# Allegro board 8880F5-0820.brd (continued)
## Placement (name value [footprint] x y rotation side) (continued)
NOREF#876  -  []  327.57 204.65 90 top
NOREF#877  -  []  96.33 238.84 0 top
NOREF#878  -  []  351.58 288.86 0 top
NOREF#879  -  []  168.13 132.17 90 top
NOREF#880  -  []  339.33 204.35 90 top
NOREF#881  -  []  310.43 243.09 90 top
NOREF#882  -  []  182.82 216.47 90 top
NOREF#883  -  []  122.15 187.53 0 top
NOREF#884  -  []  414.25 154.88 0 top
NOREF#885  -  []  465.31 186.77 0 top
NOREF#886  -  []  118.33 273.87 90 top
NOREF#887  -  []  273.5 148.65 90 top
NOREF#888  -  []  263.95 224.74 90 top
NOREF#889  -  []  313.56 144.34 90 top
NOREF#890  -  []  309.05 211.67 0 top
NOREF#891  -  []  124.1 238.84 0 top
NOREF#892  -  []  333.4 205.55 0 top
NOREF#893  -  []  272.24 243.59 90 top
NOREF#894  -  []  327.25 265.55 0 top
NOREF#895  -  []  410.52 241.11 0 top
NOREF#896  -  []  405.42 131.94 90 top
NOREF#897  -  []  317.83 257.63 0 top
NOREF#898  -  []  353.35 288.31 90 top
NOREF#899  -  []  167.7 200.54 0 top
NOREF#900  -  []  230.41 188.88 90 top
NOREF#901  -  []  167.7 233.47 90 top
NOREF#902  -  []  261.21 286.96 0 top
NOREF#903  -  []  184.47 173.11 0 top
NOREF#904  -  []  396.22 139.89 0 top
NOREF#905  -  []  392.47 272.56 90 top
NOREF#906  -  []  309.21 253.37 0 top
NOREF#907  -  []  390.53 146.88 0 top
NOREF#908  -  []  118.33 289.48 90 top
NOREF#909  -  []  379.48 222.7 90 top
NOREF#910  -  []  262.36 225.04 90 top
NOREF#911  -  []  275.3 155.38 0 top
NOREF#912  -  []  392.73 188.15 0 top
NOREF#913  -  []  166.06 203.01 90 top
NOREF#914  -  []  324.65 288.86 0 top
NOREF#915  -  []  118.99 171.65 0 top
NOREF#916  -  []  220.36 188.49 0 top
NOREF#917  -  []  351.34 245.18 0 top
NOREF#918  -  []  175.7 164.3 90 top
NOREF#919  -  []  405.93 224.66 90 top
NOREF#920  -  []  367.13 287.22 0 top
NOREF#921  -  []  256.77 225.04 90 top
NOREF#922  -  []  410.52 273.37 0 top
NOREF#923  -  []  390.53 188.15 0 top
NOREF#924  -  []  408.02 271.47 0 top
NOREF#925  -  []  343.2 172.26 90 top
NOREF#926  -  []  230.73 189.2 0 top
NOREF#927  -  []  376.98 257.11 0 top
NOREF#928  -  []  332.51 265.55 0 top
NOREF#929  -  []  339.65 205.86 90 top
NOREF#930  -  []  419.65 256.92 90 top
NOREF#931  -  []  168.69 290.01 90 top
NOREF#932  -  []  185.2 276.04 90 top
NOREF#933  -  []  201.23 219.75 90 top
NOREF#934  -  []  265.81 288.86 0 top
NOREF#935  -  []  167.7 178.86 90 top
NOREF#936  -  []  309.51 187.93 0 top
NOREF#937  -  []  223.56 245.29 90 top
NOREF#938  -  []  177.33 146.68 90 top
NOREF#939  -  []  238.45 257.01 0 top
NOREF#940  -  []  230.73 246.66 0 top
NOREF#941  -  []  118.45 239.39 0 top
NOREF#942  -  []  448.94 276.41 90 top
NOREF#943  -  []  334.29 205.56 0 top
NOREF#944  -  []  184.47 241.43 90 top
NOREF#945  -  []  419.9 154.88 0 top
NOREF#946  -  []  388.35 217.36 0 top
NOREF#947  -  []  250.49 163.52 90 top
NOREF#948  -  []  395.2 233.11 0 top
NOREF#949  -  []  272.25 241.69 0 top
NOREF#950  -  []  339.33 205.55 0 top
NOREF#951  -  []  229.05 211.67 0 top
NOREF#952  -  []  352.25 244.23 0 top
NOREF#953  -  []  373.87 171.39 0 top
NOREF#954  -  []  201.49 159.65 90 top
NOREF#955  -  []  379.52 171.39 0 top
NOREF#956  -  []  259.88 288.41 90 top
NOREF#957  -  []  100.73 238.84 0 top
NOREF#958  -  []  184.47 145.93 0 top
NOREF#959  -  []  373.83 192.28 90 top
NOREF#960  -  []  310.43 189.52 0 top
NOREF#961  -  []  337.9 246.99 0 top
NOREF#962  -  []  277.17 288.86 0 top
NOREF#963  -  []  399.99 181.42 90 top
NOREF#964  -  []  352.25 242.32 90 top
NOREF#965  -  []  117.33 247.35 90 top
NOREF#966  -  []  209.23 189.02 90 top
NOREF#967  -  []  257.09 164.74 90 top
NOREF#968  -  []  408.88 133.16 90 top
NOREF#969  -  []  254.61 264.65 90 top
NOREF#970  -  []  201.23 217.55 90 top
NOREF#971  -  []  419.47 289.12 90 top
NOREF#972  -  []  252.51 205.56 0 top
NOREF#973  -  []  192.47 205.19 90 top
NOREF#974  -  []  310.43 246.34 90 top
NOREF#975  -  []  250.73 265.56 0 top
NOREF#976  -  []  200.98 255.15 90 top
NOREF#977  -  []  403.41 209.61 0 top
NOREF#978  -  []  462.06 293.82 90 top
NOREF#979  -  []  317.83 197.63 0 top
NOREF#980  -  []  343.31 164.74 0 top
NOREF#981  -  []  333.4 265.56 90 top
NOREF#982  -  []  419.4 171.64 0 top
NOREF#983  -  []  201.23 244.98 90 top
NOREF#984  -  []  339.46 288.86 90 top
NOREF#985  -  []  310.43 194.01 0 top
NOREF#986  -  []  383.09 289.12 0 top
NOREF#987  -  []  106.11 234.24 0 top
NOREF#988  -  []  184.47 161 90 top
NOREF#989  -  []  250.73 265.56 90 top
NOREF#990  -  []  257.08 132.19 90 top
NOREF#991  -  []  410.52 289.12 0 top
NOREF#992  -  []  302.11 240.71 0 top
NOREF#993  -  []  473.7 219.66 90 top
NOREF#994  -  []  461.86 187.32 0 top
NOREF#995  -  []  184.47 200.54 90 top
NOREF#996  -  []  192.47 216.45 90 top
NOREF#997  -  []  346.69 128.87 90 top
NOREF#998  -  []  377.23 224.65 90 top
NOREF#999  -  []  251.94 204.65 90 top
NOREF#1000  -  []  352.55 185.18 0 top
NOREF#1001  -  []  334.61 264.65 90 top
NOREF#1002  -  []  371.48 249.11 0 top
NOREF#1003  -  []  463.11 230.2 0 top
NOREF#1004  -  []  405.51 209.61 0 top
NOREF#1005  -  []  417.87 257.37 0 top
NOREF#1006  -  []  265.81 296.86 0 top
NOREF#1007  -  []  124.1 231.22 0 top
NOREF#1008  -  []  199.59 230.19 90 top
NOREF#1009  -  []  320.94 211.63 90 top
NOREF#1010  -  []  275.82 296.86 0 top
NOREF#1011  -  []  332.51 204.35 90 top
NOREF#1012  -  []  312.21 144.34 0 top
NOREF#1013  -  []  396.03 180.15 0 top
NOREF#1014  -  []  192.47 209.49 90 top
NOREF#1015  -  []  327.25 205.55 0 top
NOREF#1016  -  []  341.63 255.43 90 top
NOREF#1017  -  []  401.89 163.64 0 top
NOREF#1018  -  []  246.23 173.13 0 top
NOREF#1019  -  []  239.33 243.63 90 top
NOREF#1020  -  []  410.27 257.37 0 top
NOREF#1021  -  []  383.09 241.11 0 top
NOREF#1022  -  []  352.25 182.96 0 top
NOREF#1023  -  []  266.74 143.19 0 top
NOREF#1024  -  []  405.5 289.12 90 top
NOREF#1025  -  []  310.43 247.61 90 top
NOREF#1026  -  []  478.57 277.31 90 top
NOREF#1027  -  []  115.99 130.36 90 top
NOREF#1028  -  []  414.82 281.37 0 top
NOREF#1029  -  []  378.58 289.12 90 top
NOREF#1030  -  []  408.02 239.21 0 top
NOREF#1031  -  []  419.9 288.57 90 top
NOREF#1032  -  []  330.74 164.74 0 top
NOREF#1033  -  []  194.09 214.75 90 top
NOREF#1034  -  []  331.62 205.55 0 top
NOREF#1035  -  []  330.51 288.86 0 top
NOREF#1036  -  []  172.08 275.14 90 top
NOREF#1037  -  []  175.7 150.58 90 top
NOREF#1038  -  []  155.57 289.11 90 top
NOREF#1039  -  []  453.88 195.91 0 top
NOREF#1040  -  []  395.2 297.12 0 top
NOREF#1041  -  []  309.21 247.61 0 top
NOREF#1042  -  []  385.32 178.25 90 top
NOREF#1043  -  []  297.83 174.63 90 top
NOREF#1044  -  []  237.66 224.74 0 top
NOREF#1045  -  []  221.56 231.46 0 top
NOREF#1046  -  []  352.25 182.32 90 top
NOREF#1047  -  []  300.74 286.96 90 top
NOREF#1048  -  []  275.28 290.13 90 top
NOREF#1049  -  []  201.23 229.07 90 top
NOREF#1050  -  []  400.85 249.11 0 top
NOREF#1051  -  []  209.49 175.56 90 top
NOREF#1052  -  []  387.39 297.12 0 top
NOREF#1053  -  []  249.28 165.04 90 top
NOREF#1054  -  []  396.55 273.11 0 top
NOREF#1055  -  []  386.53 148.15 90 top
NOREF#1056  -  []  383.09 257.11 0 top
NOREF#1057  -  []  272.24 182.32 90 top
NOREF#1058  -  []  217.41 273.24 90 top
NOREF#1059  -  []  270.04 280.1 0 top
NOREF#1060  -  []  106.36 190.55 0 top
NOREF#1061  -  []  395.2 265.37 0 top
NOREF#1062  -  []  272.25 242.32 90 top
NOREF#1063  -  []  343.31 224.72 0 top
NOREF#1064  -  []  473.79 234.49 90 top
NOREF#1065  -  []  118.96 179.19 0 top
NOREF#1066  -  []  418.37 289.17 90 top
NOREF#1067  -  []  230.41 193.37 90 top
NOREF#1068  -  []  394.05 255.47 0 top
NOREF#1069  -  []  127.81 175.44 90 top
NOREF#1070  -  []  450.03 225.6 0 top
NOREF#1071  -  []  352.25 243.59 90 top
NOREF#1072  -  []  167.7 260.9 90 top
NOREF#1073  -  []  167.7 187.92 90 top
NOREF#1074  -  []  167.7 227.72 90 top
NOREF#1075  -  []  310.43 187.61 90 top
NOREF#1076  -  []  175.7 205.19 90 top
NOREF#1077  -  []  390.69 241.11 0 top
NOREF#1078  -  []  247.25 265.56 0 top
NOREF#1079  -  []  415.08 139.89 0 top
NOREF#1080  -  []  330.17 165.04 90 top
NOREF#1081  -  []  251.38 163.52 90 top
NOREF#1082  -  []  318.3 163.52 90 top
NOREF#1083  -  []  94.93 190.55 0 top
NOREF#1084  -  []  333.4 265.56 0 top
NOREF#1085  -  []  168.13 159.1 90 top
NOREF#1086  -  []  166.06 148.4 90 top
NOREF#1087  -  []  108.01 222.33 0 top
NOREF#1088  -  []  367.13 271.21 0 top
NOREF#1089  -  []  396.55 225.11 0 top
NOREF#1090  -  []  311.44 288.86 0 top
NOREF#1091  -  []  368.28 297.12 0 top
NOREF#1092  -  []  237.98 225.04 90 top
NOREF#1093  -  []  248.96 164.74 0 top
NOREF#1094  -  []  318.32 131.64 0 top
NOREF#1095  -  []  230.83 224.63 0 top
NOREF#1096  -  []  303.56 173.86 90 top
NOREF#1097  -  []  401.87 139.89 0 top
NOREF#1098  -  []  192.47 222.95 90 top
NOREF#1099  -  []  352.55 189.5 0 top
NOREF#1100  -  []  475.04 195.66 0 top
NOREF#1101  -  []  238.45 197.01 0 top
NOREF#1102  -  []  327.57 264.65 90 top
NOREF#1103  -  []  282.9 147.38 0 top
NOREF#1104  -  []  247.57 204.65 90 top
NOREF#1105  -  []  271.34 189.5 0 top
NOREF#1106  -  []  209.23 236.67 90 top
NOREF#1107  -  []  247.25 265.55 0 top
NOREF#1108  -  []  107.02 174.04 90 top
NOREF#1109  -  []  377.32 188.15 0 top
NOREF#1110  -  []  404.15 257.37 0 top
NOREF#1111  -  []  377.23 289.12 0 top
NOREF#1112  -  []  404.4 225.16 90 top
NOREF#1113  -  []  93.76 271.33 90 top
NOREF#1114  -  []  119.99 214.79 0 top
NOREF#1115  -  []  309.51 186.66 0 top
NOREF#1116  -  []  223.15 211.32 90 top
NOREF#1117  -  []  334.29 265.56 90 top
NOREF#1118  -  []  309.51 249.2 0 top
NOREF#1119  -  []  310.41 247.61 90 top
NOREF#1120  -  []  343.98 288.86 0 top
NOREF#1121  -  []  75.98 290.38 90 top
NOREF#1122  -  []  209.59 147.43 90 top
NOREF#1123  -  []  423.71 181.22 90 top
NOREF#1124  -  []  182.57 185.42 90 top
NOREF#1125  -  []  209.33 215.25 90 top
NOREF#1126  -  []  182.57 226.57 0 top
NOREF#1127  -  []  215.96 248.49 0 top
NOREF#1128  -  []  167.7 219.75 90 top
NOREF#1129  -  []  252.51 204.35 90 top
NOREF#1130  -  []  305.94 296.86 0 top
NOREF#1131  -  []  184.47 229.07 90 top
NOREF#1132  -  []  342.36 223.82 90 top
NOREF#1133  -  []  192.47 168.6 90 top
NOREF#1134  -  []  75.98 271.33 90 top
NOREF#1135  -  []  419.22 257.37 90 top
NOREF#1136  -  []  184.47 217.55 90 top
NOREF#1137  -  []  481.96 276.41 90 top
NOREF#1138  -  []  300.01 288.41 90 top
NOREF#1139  -  []  418.12 257.42 90 top
NOREF#1140  -  []  415.1 163.64 0 top
NOREF#1141  -  []  327.27 131.64 90 top
NOREF#1142  -  []  230.43 253.37 90 top
NOREF#1143  -  []  468.85 259.9 90 top
NOREF#1144  -  []  248.96 224.72 0 top
NOREF#1145  -  []  396.55 257.37 0 top
NOREF#1146  -  []  388.43 163.64 0 top
NOREF#1147  -  []  118.33 271.33 90 top
NOREF#1148  -  []  475.04 239.09 0 top
NOREF#1149  -  []  200.98 258.7 90 top
NOREF#1150  -  []  411.26 209.66 90 top
NOREF#1151  -  []  329.85 224.72 0 top
NOREF#1152  -  []  326.23 173.13 0 top
NOREF#1153  -  []  298.16 248.49 0 top
NOREF#1154  -  []  387.08 188.15 0 top
NOREF#1155  -  []  107.76 238.84 0 top
NOREF#1156  -  []  199.33 185.42 0 top
NOREF#1157  -  []  167.7 190.12 90 top
NOREF#1158  -  []  110.47 178.64 0 top
NOREF#1159  -  []  184.47 149.48 90 top
NOREF#1160  -  []  273.95 147.38 90 top
NOREF#1161  -  []  201.49 161 90 top
NOREF#1162  -  []  101.82 290.38 90 top
NOREF#1163  -  []  215.96 177.06 0 top
NOREF#1164  -  []  397.8 146.33 90 top
NOREF#1165  -  []  330.73 265.56 90 top
NOREF#1166  -  []  326.43 288.31 90 top
NOREF#1167  -  []  263.31 224.72 0 top
NOREF#1168  -  []  392.21 131.94 90 top
NOREF#1169  -  []  253.4 205.55 0 top
NOREF#1170  -  []  273.09 288.31 90 top
NOREF#1171  -  []  310.41 246.34 90 top
NOREF#1172  -  []  303.15 271.32 90 top
NOREF#1173  -  []  175.7 246.08 90 top
NOREF#1174  -  []  271.04 241.69 0 top
NOREF#1175  -  []  172.08 289.11 90 top
NOREF#1176  -  []  232.25 271.67 90 top
NOREF#1177  -  []  167.7 219.75 90 top
NOREF#1178  -  []  230.41 243.09 90 top
NOREF#1179  -  []  250.74 224.74 0 top
NOREF#1180  -  []  252.83 205.86 90 top
NOREF#1181  -  []  327.25 205.56 90 top
NOREF#1182  -  []  237.66 224.72 0 top
NOREF#1183  -  []  319.33 176.03 0 top
NOREF#1184  -  []  167.7 174.46 90 top
NOREF#1185  -  []  412.36 209.61 90 top
NOREF#1186  -  []  284.79 272.65 90 top
NOREF#1187  -  []  398.65 265.37 0 top
NOREF#1188  -  []  116.01 222.33 0 top
NOREF#1189  -  []  341.63 173.83 90 top
NOREF#1190  -  []  259.33 204.35 90 top
NOREF#1191  -  []  406.65 287.22 90 top
NOREF#1192  -  []  298.24 288.86 0 top
NOREF#1193  -  []  201.23 214 0 top
NOREF#1194  -  []  192.47 177.76 90 top
NOREF#1195  -  []  272.25 189.82 0 top
NOREF#1196  -  []  248.33 187.93 0 top
NOREF#1197  -  []  346.27 129.42 0 top
NOREF#1198  -  []  249.85 164.72 0 top
NOREF#1199  -  []  332.83 265.86 90 top
NOREF#1200  -  []  385.19 257.11 0 top
NOREF#1201  -  []  242.23 173.13 90 top
NOREF#1202  -  []  394.05 287.22 0 top
NOREF#1203  -  []  310.43 253.37 0 top
NOREF#1204  -  []  393.74 131.34 90 top
NOREF#1205  -  []  463.61 214.96 0 top
NOREF#1206  -  []  263.31 164.74 0 top
NOREF#1207  -  []  383.83 194.68 90 top
NOREF#1208  -  []  215.96 248.49 0 top
NOREF#1209  -  []  385.19 289.12 0 top
NOREF#1210  -  []  167.7 244.98 90 top
NOREF#1211  -  []  259.65 264.65 90 top
NOREF#1212  -  []  372.72 161.49 0 top
NOREF#1213  -  []  259.33 205.55 0 top
NOREF#1214  -  []  304.61 144.34 0 top
NOREF#1215  -  []  465.45 273.87 90 top
NOREF#1216  -  []  308.91 139.64 0 top
NOREF#1217  -  []  301.34 286.96 0 top
NOREF#1218  -  []  239.4 296.61 0 top
NOREF#1219  -  []  182.82 148.4 90 top
NOREF#1220  -  []  127.95 195.15 0 top
NOREF#1221  -  []  352.55 245.18 0 top
NOREF#1222  -  []  352.24 182.32 90 top
NOREF#1223  -  []  229.51 249.2 0 top
NOREF#1224  -  []  249.6 224.74 90 top
NOREF#1225  -  []  371.73 289.12 0 top
NOREF#1226  -  []  369.63 273.11 0 top
NOREF#1227  -  []  177.33 187.32 90 top
NOREF#1228  -  []  552.76 299.72 0 top
NOREF#1229  -  []  127.7 231.22 0 top
NOREF#1230  -  []  106.18 160.58 90 top
NOREF#1231  -  []  182.82 189.04 90 top
NOREF#1232  -  []  304.65 211.67 0 top
NOREF#1233  -  []  398.65 249.11 0 top
NOREF#1234  -  []  312.25 271.67 90 top
NOREF#1235  -  []  310.73 193.69 0 top
NOREF#1236  -  []  397.57 131.89 0 top
NOREF#1237  -  []  167.7 241.43 90 top
NOREF#1238  -  []  278.6 147.38 0 top
NOREF#1239  -  []  166.06 162.12 90 top
NOREF#1240  -  []  330.73 205.56 0 top
NOREF#1241  -  []  251.62 265.56 90 top
NOREF#1242  -  []  167.7 178.86 90 top
NOREF#1243  -  []  393.19 271.21 90 top
NOREF#1244  -  []  230.43 187.61 0 top
NOREF#1245  -  []  182.82 162.12 90 top
NOREF#1246  -  []  221.56 239.06 0 top
NOREF#1247  -  []  168.69 276.04 90 top
NOREF#1248  -  []  485.36 259.9 90 top
NOREF#1249  -  []  413.96 182.44 90 top
NOREF#1250  -  []  167.7 256.5 90 top
NOREF#1251  -  []  172.08 272.6 90 top
NOREF#1252  -  []  386.46 139.89 0 top
NOREF#1253  -  []  256.77 163.82 90 top
NOREF#1254  -  []  329.6 164.74 90 top
NOREF#1255  -  []  192.57 256.4 90 top
NOREF#1256  -  []  263.71 288.86 0 top
NOREF#1257  -  []  410.78 131.89 0 top
NOREF#1258  -  []  351.04 245.5 0 top
NOREF#1259  -  []  332.83 264.65 90 top
NOREF#1260  -  []  379 272.56 90 top
NOREF#1261  -  []  124.39 214.79 0 top
NOREF#1262  -  []  404.24 154.88 0 top
NOREF#1263  -  []  36.1 129.71 90 top
NOREF#1264  -  []  304.65 271.67 0 top
NOREF#1265  -  []  351.04 185.5 0 top
NOREF#1266  -  []  331.06 163.82 90 top
NOREF#1267  -  []  406.94 131.34 90 top
NOREF#1268  -  []  271.34 249.5 0 top
NOREF#1269  -  []  306.71 152.34 0 top
NOREF#1270  -  []  184.89 145.38 90 top
NOREF#1271  -  []  199.84 175.58 90 top
NOREF#1272  -  []  398.53 161.74 90 top
NOREF#1273  -  []  271.82 134.74 90 top
NOREF#1274  -  []  192.57 147.18 90 top
NOREF#1275  -  []  201.23 186.57 90 top
NOREF#1276  -  []  199.33 226.57 90 top
NOREF#1277  -  []  184.47 206.29 90 top
NOREF#1278  -  []  317.66 224.74 0 top
NOREF#1279  -  []  341.63 233.83 90 top
NOREF#1280  -  []  210.86 187.32 90 top
NOREF#1281  -  []  450.03 191.31 0 top
NOREF#1282  -  []  387.39 249.11 0 top
NOREF#1283  -  []  453.88 239.34 0 top
NOREF#1284  -  []  209.49 148.63 90 top
NOREF#1285  -  []  450.03 225.6 0 top
NOREF#1286  -  []  414.82 297.12 0 top
NOREF#1287  -  []  399.8 207.46 90 top
NOREF#1288  -  []  175.7 232.37 90 top
NOREF#1289  -  []  383.09 273.11 0 top
NOREF#1290  -  []  36.1 131.91 0 top
NOREF#1291  -  []  230.73 193.69 0 top
NOREF#1292  -  []  398.65 209.36 90 top
NOREF#1293  -  []  308.36 202.16 45 top
NOREF#1294  -  []  385.19 232.85 0 top
NOREF#1295  -  []  351.34 183.91 0 top
NOREF#1296  -  []  118.7 182.93 90 top
NOREF#1297  -  []  201.23 242.78 90 top
NOREF#1298  -  []  333.4 204.35 90 top
NOREF#1299  -  []  406.65 271.21 90 top
NOREF#1300  -  []  167.7 192.32 90 top
NOREF#1301  -  []  418.37 273.42 90 top
NOREF#1302  -  []  270.04 280.1 0 top
NOREF#1303  -  []  167.7 201.89 90 top
NOREF#1304  -  []  310.41 188.88 90 top
NOREF#1305  -  []  425.23 180.72 90 top
NOREF#1306  -  []  284.36 272.1 90 top
NOREF#1307  -  []  226.44 294.64 90 top
NOREF#1308  -  []  116.27 178.64 0 top
NOREF#1309  -  []  329.85 164.74 0 top
NOREF#1310  -  []  182.82 243.9 90 top
NOREF#1311  -  []  304.61 144.34 0 top
NOREF#1312  -  []  390.94 224.9 90 top
NOREF#1313  -  []  209.23 209.49 90 top
NOREF#1314  -  []  380.59 287.22 0 top
NOREF#1315  -  []  251.33 140.14 0 top
NOREF#1316  -  []  167.7 217.55 90 top
NOREF#1317  -  []  272.25 182.32 90 top
NOREF#1318  -  []  415.61 185.72 90 top
NOREF#1319  -  []  313.98 143.89 90 top
NOREF#1320  -  []  175.7 135.17 90 top
NOREF#1321  -  []  251.06 163.82 90 top
NOREF#1322  -  []  209.59 160.9 90 top
NOREF#1323  -  []  184.89 254.6 90 top
NOREF#1324  -  []  279.7 155.38 0 top
NOREF#1325  -  []  124.61 178.64 0 top
NOREF#1326  -  []  167.7 159.65 0 top
NOREF#1327  -  []  477.24 239.09 0 top
NOREF#1328  -  []  290.64 288.86 0 top
NOREF#1329  -  []  449.99 174.46 0 top
NOREF#1330  -  []  478.57 293.82 90 top
NOREF#1331  -  []  310.41 193.37 90 top
NOREF#1332  -  []  317.66 224.72 0 top
NOREF#1333  -  []  175.8 256.4 90 top
NOREF#1334  -  []  182.57 158.5 90 top
NOREF#1335  -  []  394.66 274.38 90 top
NOREF#1336  -  []  468.85 257.36 90 top
NOREF#1337  -  []  248.96 164.72 0 top
NOREF#1338  -  []  177.33 133.47 90 top
NOREF#1339  -  []  326.43 288.41 90 top
NOREF#1340  -  []  201.23 233.47 90 top
NOREF#1341  -  []  473.6 206.05 90 top
NOREF#1342  -  []  460.93 225.6 90 top
NOREF#1343  -  []  310.43 187.61 0 top
NOREF#1344  -  []  410.52 241.11 0 top
NOREF#1345  -  []  338.11 288.86 0 top
NOREF#1346  -  []  373.87 188.15 0 top
NOREF#1347  -  []  342.36 165.04 90 top
NOREF#1348  -  []  399.67 131.89 0 top
NOREF#1349  -  []  310.43 243.09 0 top
NOREF#1350  -  []  192.47 162.1 90 top
NOREF#1351  -  []  351.04 182.96 0 top
NOREF#1352  -  []  267.84 280.1 0 top
NOREF#1353  -  []  106.76 217.73 90 top
NOREF#1354  -  []  253.4 265.56 90 top
NOREF#1355  -  []  175.8 174.36 90 top
NOREF#1356  -  []  471.21 168.33 0 top
NOREF#1357  -  []  342.68 164.74 90 top
NOREF#1358  -  []  310.83 224.63 0 top
NOREF#1359  -  []  118.7 188.08 0 top
NOREF#1360  -  []  166.06 257.62 90 top
NOREF#1361  -  []  411.09 146.88 90 top
NOREF#1362  -  []  511.59 276.41 90 top
NOREF#1363  -  []  390.94 273.16 90 top
NOREF#1364  -  []  319.33 243.63 90 top
NOREF#1365  -  []  460.93 166.93 90 top
NOREF#1366  -  []  309.51 193.69 0 top
NOREF#1367  -  []  175.8 160.9 90 top
NOREF#1368  -  []  351.34 243.91 0 top
NOREF#1369  -  []  310.43 253.37 90 top
NOREF#1370  -  []  387.08 171.64 0 top
NOREF#1371  -  []  332.51 265.56 90 top
NOREF#1372  -  []  108.01 195.15 0 top
NOREF#1373  -  []  353.35 288.41 90 top
NOREF#1374  -  []  465.81 214.96 0 top
NOREF#1375  -  []  209.49 155.13 90 top
NOREF#1376  -  []  166.06 135.19 90 top
NOREF#1377  -  []  175.7 162.1 90 top
NOREF#1378  -  []  199.33 240.28 0 top
NOREF#1379  -  []  352.24 189.18 90 top
NOREF#1380  -  []  397.8 146.43 90 top
NOREF#1381  -  []  237.83 257.63 0 top
NOREF#1382  -  []  401.89 180.15 0 top
NOREF#1383  -  []  264.72 272.65 90 top
NOREF#1384  -  []  459.28 236.14 90 top
NOREF#1385  -  []  453.88 171.53 0 top
NOREF#1386  -  []  177.33 214.75 90 top
NOREF#1387  -  []  295.96 237.06 0 top
NOREF#1388  -  []  238.3 223.52 90 top
NOREF#1389  -  []  127.95 187.53 0 top
NOREF#1390  -  []  405.5 257.37 90 top
NOREF#1391  -  []  329.85 224.74 0 top
NOREF#1392  -  []  258.2 186.67 0 top
NOREF#1393  -  []  459.28 168.33 90 top
NOREF#1394  -  []  271.04 245.5 0 top
NOREF#1395  -  []  184.47 151.68 90 top
NOREF#1396  -  []  385.36 194.18 90 top
NOREF#1397  -  []  375.22 163.39 0 top
NOREF#1398  -  []  310.43 183.09 90 top
NOREF#1399  -  []  511.59 291.28 90 top
NOREF#1400  -  []  301.56 182.89 0 top
NOREF#1401  -  []  352.93 288.86 90 top
NOREF#1402  -  []  395.07 129.99 0 top
NOREF#1403  -  []  192.47 189.02 90 top
NOREF#1404  -  []  184.89 227.17 90 top
NOREF#1405  -  []  106.76 215.26 0 top
NOREF#1406  -  []  306.27 156.63 90 top
NOREF#1407  -  []  300.36 237.06 0 top
NOREF#1408  -  []  391.96 131.89 0 top
NOREF#1409  -  []  338.2 186.67 0 top
NOREF#1410  -  []  352.25 241.69 0 top
NOREF#1411  -  []  310.43 248.88 90 top
NOREF#1412  -  []  451.68 186.77 0 top
NOREF#1413  -  []  379.52 188.15 0 top
NOREF#1414  -  []  470.71 227 90 top
NOREF#1415  -  []  369.38 241.11 0 top
NOREF#1416  -  []  301.56 190.49 0 top
NOREF#1417  -  []  259.33 264.35 90 top
NOREF#1418  -  []  343.31 224.74 0 top
NOREF#1419  -  []  259.97 204.35 90 top
NOREF#1420  -  []  354.27 131.87 90 top
NOREF#1421  -  []  245.15 288.66 90 top
NOREF#1422  -  []  167.7 149.48 90 top
NOREF#1423  -  []  229.21 246.34 0 top
NOREF#1424  -  []  209.33 242.68 90 top
NOREF#1425  -  []  388.43 146.88 0 top
NOREF#1426  -  []  251.22 253.63 0 top
NOREF#1427  -  []  456.08 195.91 0 top
NOREF#1428  -  []  415.61 179.97 90 top
NOREF#1429  -  []  263.63 223.82 90 top
NOREF#1430  -  []  175.8 215.25 90 top
NOREF#1431  -  []  250.17 163.82 90 top
NOREF#1432  -  []  119.7 231.22 0 top
NOREF#1433  -  []  111.54 290.38 90 top
NOREF#1434  -  []  302.11 180.71 0 top
NOREF#1435  -  []  279.27 288.86 0 top
NOREF#1436  -  []  175.7 141.67 90 top
NOREF#1437  -  []  310.41 248.88 90 top
NOREF#1438  -  []  369.38 257.11 0 top
NOREF#1439  -  []  317.98 225.04 90 top
NOREF#1440  -  []  308.14 296.86 0 top
NOREF#1441  -  []  397.38 163.64 90 top
NOREF#1442  -  []  310.41 243.09 90 top
NOREF#1443  -  []  310.43 193.37 90 top
NOREF#1444  -  []  284.77 288.86 0 top
NOREF#1445  -  []  226.83 269.63 90 top
NOREF#1446  -  []  184.47 233.47 90 top
NOREF#1447  -  []  342.36 163.82 90 top
NOREF#1448  -  []  310.43 193.37 0 top
NOREF#1449  -  []  330.18 182.88 0 top
NOREF#1450  -  []  11.6 261.68 90 top
NOREF#1451  -  []  371.73 281.11 0 top
NOREF#1452  -  []  254.61 204.65 90 top
NOREF#1453  -  []  339.65 264.65 90 top
NOREF#1454  -  []  373.32 181.42 90 top
NOREF#1455  -  []  472.86 166.93 90 top
NOREF#1456  -  []  277.17 288.86 0 top
NOREF#1457  -  []  383.73 202.38 90 top
NOREF#1458  -  []  110.21 214.71 0 top
NOREF#1459  -  []  400.85 265.37 0 top
NOREF#1460  -  []  409.17 297.12 0 top
NOREF#1461  -  []  384.17 163.39 90 top
NOREF#1462  -  []  318.45 257.01 0 top
NOREF#1463  -  []  313.94 286.96 90 top
NOREF#1464  -  []  155.57 275.14 90 top
NOREF#1465  -  []  201.23 200.54 0 top
NOREF#1466  -  []  120.21 178.64 0 top
NOREF#1467  -  []  333.72 204.65 90 top
NOREF#1468  -  []  456.08 186.77 0 top
NOREF#1469  -  []  412.62 249.11 0 top
NOREF#1470  -  []  177.33 242.18 90 top
NOREF#1471  -  []  334.29 265.55 0 top
NOREF#1472  -  []  331.05 265.86 90 top
NOREF#1473  -  []  253.4 205.56 90 top
NOREF#1474  -  []  315.16 290.13 90 top
NOREF#1475  -  []  400.91 207.71 0 top
NOREF#1476  -  []  404.15 289.12 0 top
NOREF#1477  -  []  115.61 211.51 90 top
NOREF#1478  -  []  175.7 216.45 90 top
NOREF#1479  -  []  299.59 288.86 90 top
NOREF#1480  -  []  257.9 186.99 0 top
NOREF#1481  -  []  354.27 134.07 90 top
NOREF#1482  -  []  461.96 174.55 0 top
NOREF#1483  -  []  220.36 177.06 0 top
NOREF#1484  -  []  122.41 178.64 0 top
NOREF#1485  -  []  260.55 136.46 90 top
NOREF#1486  -  []  473.7 176.22 90 top
NOREF#1487  -  []  168.69 292.55 90 top
NOREF#1488  -  []  230.41 247.61 90 top
NOREF#1489  -  []  330.74 224.72 0 top
NOREF#1490  -  []  461.96 217.98 0 top
NOREF#1491  -  []  396.55 225.11 0 top
NOREF#1492  -  []  201.49 176.66 90 top
NOREF#1493  -  []  331.62 264.35 90 top
NOREF#1494  -  []  528.1 276.41 90 top
NOREF#1495  -  []  384.08 209.16 90 top
NOREF#1496  -  []  168.13 172.56 90 top
NOREF#1497  -  []  108.01 214.71 0 top
NOREF#1498  -  []  460.93 234.74 90 top
NOREF#1499  -  []  229.51 246.66 0 top
NOREF#1500  -  []  251.62 205.56 0 top
NOREF#1501  -  []  230.41 186.34 90 top
NOREF#1502  -  []  225.83 264.31 0 top
NOREF#1503  -  []  209.33 201.79 90 top
NOREF#1504  -  []  295.19 271.65 90 top
NOREF#1505  -  []  390.53 180.15 0 top
NOREF#1506  -  []  201.49 149.73 90 top
NOREF#1507  -  []  230.43 188.88 90 top
NOREF#1508  -  []  328.96 224.72 0 top
NOREF#1509  -  []  511.59 293.82 90 top
NOREF#1510  -  []  405.93 272.56 90 top
NOREF#1511  -  []  249.15 296.86 0 top
NOREF#1512  -  []  184.47 174.46 90 top
NOREF#1513  -  []  327.25 264.35 90 top
NOREF#1514  -  []  268.94 272.1 0 top
NOREF#1515  -  []  236.27 289.16 90 top
NOREF#1516  -  []  327.25 265.55 0 top
NOREF#1517  -  []  249.85 164.74 0 top
NOREF#1518  -  []  234.33 228.13 90 top
NOREF#1519  -  []  104.18 191.95 90 top
NOREF#1520  -  []  407.71 217.61 0 top
NOREF#1521  -  []  222.67 298 90 top
NOREF#1522  -  []  175.7 259.8 90 top
NOREF#1523  -  []  167.7 214 0 top
NOREF#1524  -  []  234.33 168.13 90 top
NOREF#1525  -  []  375.73 193.43 0 top
NOREF#1526  -  []  367.48 225.87 90 top
NOREF#1527  -  []  413.51 207.71 90 top
NOREF#1528  -  []  219.81 273.69 90 top
NOREF#1529  -  []  373.32 164.66 90 top
NOREF#1530  -  []  300.36 177.06 0 top
NOREF#1531  -  []  418.12 241.11 0 top
NOREF#1532  -  []  416.03 179.42 90 top
NOREF#1533  -  []  221.56 171.46 0 top
NOREF#1534  -  []  184.47 165.4 90 top
NOREF#1535  -  []  247.25 204.35 90 top
NOREF#1536  -  []  167.7 192.32 90 top
NOREF#1537  -  []  451.64 222.5 0 top
NOREF#1538  -  []  192.57 228.97 90 top
NOREF#1539  -  []  482.64 235.89 90 top
NOREF#1540  -  []  216.96 180.71 0 top
NOREF#1541  -  []  385.19 265.11 0 top
NOREF#1542  -  []  330.74 164.72 0 top
NOREF#1543  -  []  254.61 265.86 90 top
NOREF#1544  -  []  248.21 132.69 90 top
NOREF#1545  -  []  175.7 250.38 90 top
NOREF#1546  -  []  471.59 130.36 90 top
NOREF#1547  -  []  315.7 296.86 0 top
NOREF#1548  -  []  456.08 230.2 0 top
NOREF#1549  -  []  253.4 264.35 90 top
NOREF#1550  -  []  465.31 230.2 0 top
NOREF#1551  -  []  399.39 178.25 0 top
NOREF#1552  -  []  463.61 179.15 0 top
NOREF#1553  -  []  237.98 165.04 90 top
NOREF#1554  -  []  230.43 186.34 90 top
NOREF#1555  -  []  192.47 230.17 90 top
NOREF#1556  -  []  237.98 223.82 90 top
NOREF#1557  -  []  459.28 183.57 0 top
NOREF#1558  -  []  106.11 234.24 0 top
NOREF#1559  -  []  412.24 144.98 90 top
NOREF#1560  -  []  406.52 131.89 90 top
NOREF#1561  -  []  354.08 286.96 90 top
NOREF#1562  -  []  511.59 273.87 90 top
NOREF#1563  -  []  403.99 188.15 0 top
NOREF#1564  -  []  329.6 163.52 90 top
NOREF#1565  -  []  301.95 290.13 90 top
NOREF#1566  -  []  411.99 178.25 90 top
NOREF#1567  -  []  461.96 217.98 0 top
NOREF#1568  -  []  118.7 217.73 90 top
NOREF#1569  -  []  226.83 209.63 90 top
NOREF#1570  -  []  94.68 234.24 0 top
NOREF#1571  -  []  230.43 249.52 0 top
NOREF#1572  -  []  167.7 159.65 90 top
NOREF#1573  -  []  201.23 186.57 0 top
NOREF#1574  -  []  209.23 195.52 90 top
NOREF#1575  -  []  230.73 253.69 0 top
NOREF#1576  -  []  194.09 146.68 90 top
NOREF#1577  -  []  369.38 224.6 0 top
NOREF#1578  -  []  115.61 191.95 0 top
NOREF#1579  -  []  230.43 183.09 0 top
NOREF#1580  -  []  272.25 249.82 0 top
NOREF#1581  -  []  256.45 224.74 0 top
NOREF#1582  -  []  317.98 163.82 90 top
NOREF#1583  -  []  272.55 189.5 0 top
NOREF#1584  -  []  230.43 188.88 0 top
NOREF#1585  -  []  175.7 189.02 90 top
NOREF#1586  -  []  200.98 255.15 0 top
NOREF#1587  -  []  272.8 145.48 90 top
NOREF#1588  -  []  184.47 204.09 90 top
NOREF#1589  -  []  262.34 143.19 0 top
NOREF#1590  -  []  388.43 180.15 0 top
NOREF#1591  -  []  168.13 240.88 90 top
NOREF#1592  -  []  166.06 243.9 90 top
NOREF#1593  -  []  66.26 273.87 90 top
NOREF#1594  -  []  406.44 154.88 0 top
NOREF#1595  -  []  303.56 185.29 90 top
NOREF#1596  -  []  272.25 185.5 0 top
NOREF#1597  -  []  352.25 184.23 0 top
NOREF#1598  -  []  342.08 290.13 90 top
NOREF#1599  -  []  192.47 236.67 90 top
NOREF#1600  -  []  448.94 292.92 90 top
NOREF#1601  -  []  273.95 155.38 0 top
NOREF#1602  -  []  460.93 210.36 90 top
NOREF#1603  -  []  379.48 255.21 90 top
NOREF#1604  -  []  274.67 286.96 0 top
NOREF#1605  -  []  66.26 290.38 90 top
NOREF#1606  -  []  417.7 154.88 0 top
NOREF#1607  -  []  397.57 131.89 0 top
NOREF#1608  -  []  394.05 271.21 0 top
NOREF#1609  -  []  318.32 131.64 0 top
NOREF#1610  -  []  288.14 286.96 0 top
NOREF#1611  -  []  392.47 240.56 90 top
NOREF#1612  -  []  418.12 289.12 0 top
NOREF#1613  -  []  230.43 248.88 90 top
NOREF#1614  -  []  461.96 166.93 0 top
NOREF#1615  -  []  272.25 244.23 0 top
NOREF#1616  -  []  336.45 224.74 0 top
NOREF#1617  -  []  410.52 241.11 0 top
NOREF#1618  -  []  375.22 163.39 0 top
NOREF#1619  -  []  318.3 223.52 90 top
NOREF#1620  -  []  177.33 160.4 90 top
NOREF#1621  -  []  182.82 257.62 90 top
NOREF#1622  -  []  124.35 187.53 0 top
NOREF#1623  -  []  218.16 188.49 0 top
NOREF#1624  -  []  465.81 179.15 0 top
NOREF#1625  -  []  247.25 265.55 0 top
NOREF#1626  -  []  201.49 173.11 90 top
NOREF#1627  -  []  389.7 209.36 0 top
NOREF#1628  -  []  192.47 218.65 90 top
NOREF#1629  -  []  119.7 238.84 0 top
NOREF#1630  -  []  290.11 280.1 0 top
NOREF#1631  -  []  112.67 171.02 0 top
NOREF#1632  -  []  257.09 224.74 90 top
NOREF#1633  -  []  310.73 249.2 0 top
NOREF#1634  -  []  127.3 228.02 90 top
NOREF#1635  -  []  241.82 227.13 90 top
NOREF#1636  -  []  396.28 180.2 90 top
NOREF#1637  -  []  167.7 200.54 90 top
NOREF#1638  -  []  240.5 288.61 0 top
NOREF#1639  -  []  112.67 178.64 0 top
NOREF#1640  -  []  167.7 260.9 90 top
NOREF#1641  -  []  182.57 171.96 0 top
NOREF#1642  -  []  518.38 257.36 90 top
NOREF#1643  -  []  261.63 173.83 90 top
NOREF#1644  -  []  381.74 232.85 0 top
NOREF#1645  -  []  327.25 265.56 0 top
NOREF#1646  -  []  118.99 171.65 0 top
NOREF#1647  -  []  230.43 247.61 0 top
NOREF#1648  -  []  289.01 272.1 0 top
NOREF#1649  -  []  330.73 204.35 90 top
NOREF#1650  -  []  175.8 133.97 90 top
NOREF#1651  -  []  376.23 209.11 0 top
NOREF#1652  -  []  343.95 163.52 90 top
NOREF#1653  -  []  342.36 225.04 90 top
NOREF#1654  -  []  468.01 179.15 0 top
NOREF#1655  -  []  485.36 289.48 90 top
NOREF#1656  -  []  184.47 260.9 90 top
NOREF#1657  -  []  351.34 249.5 0 top
NOREF#1658  -  []  219.76 297.18 0 top
NOREF#1659  -  []  310.83 164.63 0 top
NOREF#1660  -  []  300.36 248.49 0 top
NOREF#1661  -  []  272.24 241.05 90 top
NOREF#1662  -  []  319.33 183.63 90 top
NOREF#1663  -  []  254.29 265.56 0 top
NOREF#1664  -  []  396.28 146.93 90 top
NOREF#1665  -  []  405.93 288.57 90 top
NOREF#1666  -  []  331.38 224.74 90 top
NOREF#1667  -  []  528.1 259.9 90 top
NOREF#1668  -  []  279.27 296.86 0 top
NOREF#1669  -  []  295.96 177.06 0 top
NOREF#1670  -  []  393.19 239.21 90 top
NOREF#1671  -  []  273.59 272.15 90 top
NOREF#1672  -  []  253.53 140.14 0 top
NOREF#1673  -  []  230.41 187.61 90 top
NOREF#1674  -  []  259.97 264.35 90 top
NOREF#1675  -  []  388.43 180.15 0 top
NOREF#1676  -  []  339.97 264.35 90 top
NOREF#1677  -  []  224.65 211.67 0 top
NOREF#1678  -  []  396.55 225.11 0 top
NOREF#1679  -  []  471.21 219.38 90 top
NOREF#1680  -  []  168.13 199.99 90 top
NOREF#1681  -  []  343.83 231.63 90 top
NOREF#1682  -  []  419.9 240.66 90 top
NOREF#1683  -  []  401.87 194.18 90 top
NOREF#1684  -  []  66.26 271.33 90 top
NOREF#1685  -  []  413.71 148.15 90 top
NOREF#1686  -  []  127.7 238.84 0 top
NOREF#1687  -  []  325.92 131.64 0 top
NOREF#1688  -  []  343.2 232.26 90 top
NOREF#1689  -  []  271.04 249.82 0 top
NOREF#1690  -  []  251.05 205.86 90 top
NOREF#1691  -  []  373.83 192.28 0 top
NOREF#1692  -  []  251.38 164.74 90 top
NOREF#1693  -  []  238.3 288.61 0 top
NOREF#1694  -  []  399.07 208.81 90 top
NOREF#1695  -  []  96.33 238.84 0 top
NOREF#1696  -  []  258.61 131.69 90 top
NOREF#1697  -  []  368.03 265.11 0 top
NOREF#1698  -  []  286.55 288.31 90 top
NOREF#1699  -  []  251.62 265.55 0 top
NOREF#1700  -  []  201.91 172.56 90 top
NOREF#1701  -  []  453.88 214.96 0 top
NOREF#1702  -  []  408.92 265.37 0 top
NOREF#1703  -  []  377.23 241.16 90 top
NOREF#1704  -  []  184.47 163.2 90 top
NOREF#1705  -  []  107.18 246.83 90 top
NOREF#1706  -  []  115.36 235.64 90 top
NOREF#1707  -  []  177.33 228.47 90 top
NOREF#1708  -  []  346.27 135.17 90 top
NOREF#1709  -  []  301.56 231.46 0 top
NOREF#1710  -  []  528.1 257.36 90 top
NOREF#1711  -  []  339.33 205.55 0 top
NOREF#1712  -  []  238.3 163.52 90 top
NOREF#1713  -  []  165.8 144.78 90 top
NOREF#1714  -  []  352.25 185.5 0 top
NOREF#1715  -  []  475.36 127 90 top
NOREF#1716  -  []  167.7 255.15 0 top
NOREF#1717  -  []  409.17 249.11 0 top
NOREF#1718  -  []  167.7 186.57 0 top
NOREF#1719  -  []  459.28 183.57 90 top
NOREF#1720  -  []  451.64 179.06 0 top
NOREF#1721  -  []  247.89 204.35 90 top
NOREF#1722  -  []  317.66 164.72 0 top
NOREF#1723  -  []  261.63 255.43 90 top
NOREF#1724  -  []  327.57 265.86 90 top
NOREF#1725  -  []  128.24 171.1 0 top
NOREF#1726  -  []  463.11 186.77 0 top
NOREF#1727  -  []  209.49 162.1 90 top
NOREF#1728  -  []  342.63 296.86 0 top
NOREF#1729  -  []  329.28 225.04 90 top
NOREF#1730  -  []  339.65 204.65 90 top
NOREF#1731  -  []  404.4 289.17 90 top
NOREF#1732  -  []  392.47 288.57 90 top
NOREF#1733  -  []  175.7 264.1 90 top
NOREF#1734  -  []  392.47 272.66 90 top
NOREF#1735  -  []  217.41 273.24 0 top
NOREF#1736  -  []  199.59 189.04 90 top
NOREF#1737  -  []  451.68 214.96 0 top
NOREF#1738  -  []  272.55 185.18 0 top
NOREF#1739  -  []  184.47 247.18 90 top
NOREF#1740  -  []  247.25 205.55 0 top
NOREF#1741  -  []  404.4 257.42 90 top
NOREF#1742  -  []  352.24 244.86 90 top
NOREF#1743  -  []  326.17 131.69 90 top
NOREF#1744  -  []  401.89 180.15 0 top
NOREF#1745  -  []  122.15 222.33 0 top
NOREF#1746  -  []  453.84 179.06 0 top
NOREF#1747  -  []  453.88 230.2 0 top
NOREF#1748  -  []  229.21 183.09 0 top
NOREF#1749  -  []  331.06 225.04 90 top
NOREF#1750  -  []  375.73 193.43 90 top
NOREF#1751  -  []  259.33 265.55 0 top
NOREF#1752  -  []  229.51 247.93 0 top
NOREF#1753  -  []  412.37 265.37 0 top
NOREF#1754  -  []  127.95 222.33 0 top
NOREF#1755  -  []  330.73 205.56 90 top
NOREF#1756  -  []  333.33 241.33 90 top
NOREF#1757  -  []  107.02 171.57 0 top
NOREF#1758  -  []  410.52 289.12 0 top
NOREF#1759  -  []  390.59 195.9 90 top
NOREF#1760  -  []  339.33 205.56 0 top
NOREF#1761  -  []  262.68 224.74 90 top
NOREF#1762  -  []  251.05 264.65 90 top
NOREF#1763  -  []  343.98 288.86 0 top
NOREF#1764  -  []  201.91 159.1 90 top
NOREF#1765  -  []  352.25 189.18 90 top
NOREF#1766  -  []  471.21 219.38 0 top
NOREF#1767  -  []  215.96 188.49 0 top
NOREF#1768  -  []  342.68 223.52 90 top
NOREF#1769  -  []  167.7 151.68 90 top
NOREF#1770  -  []  201.49 174.46 90 top
NOREF#1771  -  []  271.34 183.91 0 top
NOREF#1772  -  []  182.57 254 0 top
NOREF#1773  -  []  383.09 289.12 0 top
NOREF#1774  -  []  456.08 214.96 0 top
NOREF#1775  -  []  302.71 132.91 90 top
NOREF#1776  -  []  472.86 174.55 90 top
NOREF#1777  -  []  262.04 164.74 0 top
NOREF#1778  -  []  116.27 171.02 0 top
NOREF#1779  -  []  119.95 222.33 0 top
NOREF#1780  -  []  453.88 186.77 0 top
NOREF#1781  -  []  106.03 217.88 90 top
NOREF#1782  -  []  199.33 199.39 90 top
NOREF#1783  -  []  184.47 190.12 90 top
NOREF#1784  -  []  518.38 292.92 90 top
NOREF#1785  -  []  272.55 243.91 0 top
NOREF#1786  -  []  410.27 257.37 0 top
NOREF#1787  -  []  263.31 224.74 0 top
NOREF#1788  -  []  277.17 288.86 0 top
NOREF#1789  -  []  318.3 224.74 90 top
NOREF#1790  -  []  459.28 227 0 top
NOREF#1791  -  []  418.63 131.94 90 top
NOREF#1792  -  []  263.31 164.72 0 top
NOREF#1793  -  []  352.25 189.82 0 top
NOREF#1794  -  []  369.38 241.11 0 top
NOREF#1795  -  []  352.25 249.82 0 top
NOREF#1796  -  []  254.8 296.86 0 top
NOREF#1797  -  []  394.46 129.99 90 top
NOREF#1798  -  []  404.24 146.88 0 top
NOREF#1799  -  []  165.8 185.42 90 top
NOREF#1800  -  []  283.91 273.37 90 top
NOREF#1801  -  []  295.96 188.49 0 top
NOREF#1802  -  []  199.59 243.9 90 top
NOREF#1803  -  []  412.88 131.89 0 top
NOREF#1804  -  []  343.63 165.04 90 top
NOREF#1805  -  []  463.61 214.96 0 top
NOREF#1806  -  []  226.85 271.67 0 top
NOREF#1807  -  []  406.95 131.44 90 top
NOREF#1808  -  []  450.03 234.74 0 top
NOREF#1809  -  []  331.62 205.56 90 top
NOREF#1810  -  []  331.54 252.73 90 top
NOREF#1811  -  []  234.7 286.71 90 top
NOREF#1812  -  []  409.43 139.89 0 top
NOREF#1813  -  []  397.38 180.15 90 top
NOREF#1814  -  []  403.99 171.64 0 top
NOREF#1815  -  []  166.06 216.47 90 top
NOREF#1816  -  []  254.29 204.35 90 top
NOREF#1817  -  []  309.51 247.93 0 top
NOREF#1818  -  []  263.95 164.74 90 top
NOREF#1819  -  []  165.8 131.57 90 top
NOREF#1820  -  []  405.93 256.82 90 top
NOREF#1821  -  []  272.24 249.18 90 top
NOREF#1822  -  []  177.33 201.29 90 top
NOREF#1823  -  []  337.9 246.35 90 top
NOREF#1824  -  []  337.09 164.74 90 top
NOREF#1825  -  []  175.8 242.68 90 top
NOREF#1826  -  []  450.03 210.36 0 top
NOREF#1827  -  []  320.83 254.63 0 top
NOREF#1828  -  []  331.05 205.86 90 top
NOREF#1829  -  []  328.62 290.13 90 top
NOREF#1830  -  []  371.48 241.11 0 top
NOREF#1831  -  []  252.6 288.86 0 top
NOREF#1832  -  []  250.18 242.88 0 top
NOREF#1833  -  []  417.2 163.64 0 top
NOREF#1834  -  []  209.23 218.65 90 top
NOREF#1835  -  []  260.99 143.19 0 top
NOREF#1836  -  []  201.21 276.04 90 top
NOREF#1837  -  []  229.21 253.37 0 top
NOREF#1838  -  []  263.95 163.52 90 top
NOREF#1839  -  []  385.19 241.11 0 top
NOREF#1840  -  []  373.68 249.11 0 top
NOREF#1841  -  []  184.47 159.65 90 top
NOREF#1842  -  []  250.73 205.56 90 top
NOREF#1843  -  []  346.08 296.86 0 top
NOREF#1844  -  []  279.7 155.38 0 top
NOREF#1845  -  []  184.89 159.1 90 top
NOREF#1846  -  []  271.34 249.5 0 top
NOREF#1847  -  []  501.87 273.87 90 top
NOREF#1848  -  []  175.7 137.37 90 top
NOREF#1849  -  []  451.68 230.2 0 top
NOREF#1850  -  []  479.44 195.66 0 top
NOREF#1851  -  []  352.25 245.5 0 top
NOREF#1852  -  []  459.24 219.3 0 top
NOREF#1853  -  []  373.73 207.21 0 top
NOREF#1854  -  []  310.43 186.34 0 top
NOREF#1855  -  []  420.62 287.22 90 top
NOREF#1856  -  []  333.4 265.55 0 top
NOREF#1857  -  []  201.49 147.53 90 top
NOREF#1858  -  []  387.8 210.63 90 top
NOREF#1859  -  []  272.24 184.86 90 top
NOREF#1860  -  []  304.61 131.64 0 top
NOREF#1861  -  []  247.25 205.56 0 top
NOREF#1862  -  []  309.51 183.41 0 top
NOREF#1863  -  []  249.85 224.72 0 top
NOREF#1864  -  []  303.84 288.86 0 top
NOREF#1865  -  []  330.73 265.55 0 top
NOREF#1866  -  []  122.19 214.79 0 top
NOREF#1867  -  []  330.51 288.86 0 top
NOREF#1868  -  []  340.61 286.96 90 top
NOREF#1869  -  []  310.73 187.93 0 top
NOREF#1870  -  []  231.15 219.63 90 top
NOREF#1871  -  []  184.89 213.45 90 top
NOREF#1872  -  []  201.49 163.2 90 top
NOREF#1873  -  []  251.86 192.43 90 top
NOREF#1874  -  []  409.74 146.88 0 top
NOREF#1875  -  []  259.65 264.65 90 top
NOREF#1876  -  []  331.06 165.04 90 top
NOREF#1877  -  []  259.88 288.31 90 top
NOREF#1878  -  []  223.56 185.29 90 top
NOREF#1879  -  []  247.25 205.55 0 top
NOREF#1880  -  []  93.76 273.87 90 top
NOREF#1881  -  []  239.33 236.03 0 top
NOREF#1882  -  []  118.96 179.19 0 top
NOREF#1883  -  []  377.48 273.16 90 top
NOREF#1884  -  []  385.19 281.11 0 top
NOREF#1885  -  []  413.71 178.82 90 top
NOREF#1886  -  []  184.47 186.57 90 top
NOREF#1887  -  []  167.7 165.4 90 top
NOREF#1888  -  []  250.17 225.04 90 top
NOREF#1889  -  []  392.24 193.43 0 top
NOREF#1890  -  []  229.51 243.41 0 top
NOREF#1891  -  []  453.84 222.5 0 top
NOREF#1892  -  []  388.43 180.15 0 top
NOREF#1893  -  []  93.76 290.38 90 top
NOREF#1894  -  []  310.43 248.88 90 top
NOREF#1895  -  []  395.67 133.16 90 top
NOREF#1896  -  []  331.62 265.55 0 top
NOREF#1897  -  []  352.25 181.69 0 top
NOREF#1898  -  []  201.49 178.86 90 top
NOREF#1899  -  []  303.56 233.86 90 top
NOREF#1900  -  []  369.63 289.12 0 top
NOREF#1901  -  []  404.4 273.16 90 top
NOREF#1902  -  []  118.96 174.04 90 top
NOREF#1903  -  []  331.38 223.52 90 top
NOREF#1904  -  []  201.91 145.63 90 top
NOREF#1905  -  []  384.36 131.89 0 top
NOREF#1906  -  []  352.55 249.5 0 top
NOREF#1907  -  []  283.21 282 0 top
NOREF#1908  -  []  415.6 146.88 0 top
NOREF#1909  -  []  257.09 163.52 90 top
NOREF#1910  -  []  417.2 171.64 0 top
NOREF#1911  -  []  182.57 199.39 90 top
NOREF#1912  -  []  379 288.57 90 top
NOREF#1913  -  []  405.93 256.92 90 top
NOREF#1914  -  []  200.98 260.9 90 top
NOREF#1915  -  []  383.09 241.11 0 top
NOREF#1916  -  []  271.56 288.91 90 top
NOREF#1917  -  []  254.29 265.55 0 top
NOREF#1918  -  []  254.29 205.56 90 top
NOREF#1919  -  []  118.33 286.94 90 top
NOREF#1920  -  []  222.11 180.71 0 top
NOREF#1921  -  []  319.15 288.86 0 top
NOREF#1922  -  []  330.73 265.56 0 top
NOREF#1923  -  []  217.41 213.24 90 top
NOREF#1924  -  []  374.08 195.9 90 top
NOREF#1925  -  []  201.49 151.93 90 top
NOREF#1926  -  []  330.73 205.55 0 top
NOREF#1927  -  []  310.43 246.34 0 top
NOREF#1928  -  []  518.38 273.87 90 top
NOREF#1929  -  []  375.22 180.15 0 top
NOREF#1930  -  []  381.2 258.38 90 top
NOREF#1931  -  []  309.21 246.34 0 top
NOREF#1932  -  []  424.98 146.43 90 top
NOREF#1933  -  []  230.83 164.63 0 top
NOREF#1934  -  []  165.8 226.57 0 top
NOREF#1935  -  []  184.47 255.15 90 top
NOREF#1936  -  []  410.52 273.37 0 top
NOREF#1937  -  []  192.47 246.08 90 top
NOREF#1938  -  []  331.94 265.86 90 top
NOREF#1939  -  []  415.61 179.97 0 top
NOREF#1940  -  []  184.47 159.65 0 top
NOREF#1941  -  []  230.43 246.34 0 top
NOREF#1942  -  []  122.44 171.1 0 top
NOREF#1943  -  []  313.98 131.19 90 top
NOREF#1944  -  []  108.27 171.02 0 top
NOREF#1945  -  []  240.94 211.63 90 top
NOREF#1946  -  []  247.25 205.56 90 top
NOREF#1947  -  []  237.98 163.82 90 top
NOREF#1948  -  []  331.62 265.56 0 top
NOREF#1949  -  []  194.09 173.86 90 top
NOREF#1950  -  []  459.24 175.86 0 top
NOREF#1951  -  []  336.45 224.72 0 top
NOREF#1952  -  []  259.65 204.65 90 top
NOREF#1953  -  []  330.49 224.74 90 top
NOREF#1954  -  []  392.47 256.66 90 top
NOREF#1955  -  []  372.72 178.25 0 top
NOREF#1956  -  []  115.61 191.95 90 top
NOREF#1957  -  []  343.63 223.82 90 top
NOREF#1958  -  []  330.18 242.88 0 top
NOREF#1959  -  []  230.43 187.61 90 top
NOREF#1960  -  []  297.71 276.09 0 top
NOREF#1961  -  []  415.1 163.64 0 top
NOREF#1962  -  []  184.47 242.78 90 top
NOREF#1963  -  []  340.83 234.63 90 top
NOREF#1964  -  []  462.06 274.77 90 top
NOREF#1965  -  []  459.28 211.76 90 top
NOREF#1966  -  []  192.47 232.37 90 top
NOREF#1967  -  []  298.13 214.06 90 top
NOREF#1968  -  []  201.23 214 90 top
NOREF#1969  -  []  253.4 205.56 0 top
NOREF#1970  -  []  332.51 264.35 90 top
NOREF#1971  -  []  175.8 201.79 90 top
NOREF#1972  -  []  93.02 247.21 90 top
NOREF#1973  -  []  518.38 276.41 90 top
NOREF#1974  -  []  451.68 171.53 0 top
NOREF#1975  -  []  392.73 171.64 0 top
NOREF#1976  -  []  412.88 139.89 0 top
NOREF#1977  -  []  229.21 186.34 0 top
NOREF#1978  -  []  272.24 189.18 90 top
NOREF#1979  -  []  346.27 129.42 90 top
NOREF#1980  -  []  326.23 233.13 0 top
NOREF#1981  -  []  175.7 218.65 90 top
NOREF#1982  -  []  387.08 154.88 0 top
NOREF#1983  -  []  252.51 265.55 0 top
NOREF#1984  -  []  167.7 132.72 0 top
NOREF#1985  -  []  184.47 147.28 90 top
NOREF#1986  -  []  300.11 273.24 90 top
NOREF#1987  -  []  400.54 188.15 0 top
NOREF#1988  -  []  334.61 204.65 90 top
NOREF#1989  -  []  175.7 191.22 90 top
NOREF#1990  -  []  259.33 265.56 90 top
NOREF#1991  -  []  253.4 204.35 90 top
NOREF#1992  -  []  230.41 248.88 90 top
NOREF#1993  -  []  296.96 180.71 0 top
NOREF#1994  -  []  112.41 195.15 0 top
NOREF#1995  -  []  478.57 291.28 90 top
NOREF#1996  -  []  250.49 224.74 90 top
NOREF#1997  -  []  396.55 241.11 0 top
NOREF#1998  -  []  230.43 253.37 90 top
NOREF#1999  -  []  398.65 233.11 0 top
NOREF#2000  -  []  175.7 236.67 90 top
NOREF#2001  -  []  470.79 128.27 0 top
NOREF#2002  -  []  295.96 177.06 0 top
NOREF#2003  -  []  343.95 223.52 90 top
NOREF#2004  -  []  167.7 204.09 90 top
NOREF#2005  -  []  399.07 208.91 90 top
NOREF#2006  -  []  309.21 243.09 0 top
NOREF#2007  -  []  230.73 249.2 0 top
NOREF#2008  -  []  225.83 204.31 0 top
NOREF#2009  -  []  383.09 257.11 0 top
NOREF#2010  -  []  239.33 176.03 90 top
NOREF#2011  -  []  259.84 133.29 90 top
NOREF#2012  -  []  298.16 188.49 0 top
NOREF#2013  -  []  351.34 249.5 0 top
NOREF#2014  -  []  182.57 240.28 0 top
NOREF#2015  -  []  449.99 217.9 0 top
NOREF#2016  -  []  378.75 240.66 90 top
NOREF#2017  -  []  167.7 136.27 90 top
NOREF#2018  -  []  263.14 282 0 top
NOREF#2019  -  []  194.09 242.18 90 top
NOREF#2020  -  []  274.37 147.93 90 top
NOREF#2021  -  []  411.26 163.09 90 top
NOREF#2022  -  []  201.23 192.32 90 top
NOREF#2023  -  []  167.7 151.68 90 top
NOREF#2024  -  []  229.21 188.88 0 top
NOREF#2025  -  []  118.7 190.55 90 top
NOREF#2026  -  []  405.5 225.11 90 top
NOREF#2027  -  []  334.29 205.56 90 top
NOREF#2028  -  []  201.23 219.75 90 top
NOREF#2029  -  []  308.36 262.16 45 top
NOREF#2030  -  []  259.33 205.55 0 top
NOREF#2031  -  []  463.61 222.58 0 top
NOREF#2032  -  []  406.65 223.21 90 top
NOREF#2033  -  []  412.37 257.37 0 top
NOREF#2034  -  []  405.51 217.61 0 top
NOREF#2035  -  []  293.31 272.1 0 top
NOREF#2036  -  []  262.36 223.82 90 top
NOREF#2037  -  []  336.77 165.04 90 top
NOREF#2038  -  []  192.57 187.82 90 top
NOREF#2039  -  []  351.34 182.64 0 top
NOREF#2040  -  []  165.8 158.5 90 top
NOREF#2041  -  []  242.23 173.13 0 top
NOREF#2042  -  []  108.27 171.02 0 top
NOREF#2043  -  []  201.23 227.72 0 top
NOREF#2044  -  []  235.4 289.88 90 top
NOREF#2045  -  []  276.4 147.38 0 top
NOREF#2046  -  []  192.47 250.38 90 top
NOREF#2047  -  []  483.04 195.66 0 top
NOREF#2048  -  []  399.64 144.98 0 top
NOREF#2049  -  []  379.73 271.21 90 top
NOREF#2050  -  []  463.61 179.15 0 top
NOREF#2051  -  []  377.32 163.39 0 top
NOREF#2052  -  []  422.95 163.69 90 top
NOREF#2053  -  []  309.05 271.67 0 top
NOREF#2054  -  []  375.22 180.15 0 top
NOREF#2055  -  []  482.64 192.46 90 top
NOREF#2056  -  []  101.82 271.33 90 top
NOREF#2057  -  []  120.24 171.1 0 top
NOREF#2058  -  []  251.94 205.86 90 top
NOREF#2059  -  []  167.7 176.66 90 top
NOREF#2060  -  []  351.04 244.23 0 top
NOREF#2061  -  []  230.43 254.01 0 top
NOREF#2062  -  []  371.48 224.6 0 top
NOREF#2063  -  []  252.51 205.55 0 top
NOREF#2064  -  []  194.09 228.47 90 top
NOREF#2065  -  []  201.23 206.29 90 top
NOREF#2066  -  []  406.65 239.21 90 top
NOREF#2067  -  []  328.33 187.93 0 top
NOREF#2068  -  []  475.04 195.66 0 top
NOREF#2069  -  []  209.23 232.37 90 top
NOREF#2070  -  []  199.08 254 0 top
NOREF#2071  -  []  397.57 131.89 0 top
NOREF#2072  -  []  83.77 247.51 90 top
NOREF#2073  -  []  192.57 215.25 90 top
NOREF#2074  -  []  313.98 131.09 90 top
NOREF#2075  -  []  184.47 192.32 90 top
NOREF#2076  -  []  341.63 195.43 90 top
NOREF#2077  -  []  465.81 171.53 0 top
NOREF#2078  -  []  333.72 265.86 90 top
NOREF#2079  -  []  378.75 224.15 90 top
NOREF#2080  -  []  385.93 144.98 0 top
NOREF#2081  -  []  239.33 236.03 90 top
NOREF#2082  -  []  392.24 194.78 90 top
NOREF#2083  -  []  209.49 164.3 90 top
NOREF#2084  -  []  184.47 214 90 top
NOREF#2085  -  []  328.33 247.93 0 top
NOREF#2086  -  []  284.36 280.1 0 top
NOREF#2087  -  []  398.65 273.11 0 top
NOREF#2088  -  []  199.84 162.12 90 top
NOREF#2089  -  []  472.86 210.36 90 top
NOREF#2090  -  []  378.75 224.05 90 top
NOREF#2091  -  []  237.57 269.63 90 top
NOREF#2092  -  []  495.08 274.77 90 top
NOREF#2093  -  []  465.45 292.92 90 top
NOREF#2094  -  []  168.69 273.5 90 top
NOREF#2095  -  []  471.21 175.95 0 top
NOREF#2096  -  []  265.64 135.19 0 top
NOREF#2097  -  []  378.75 256.56 90 top
NOREF#2098  -  []  250.18 182.88 0 top
NOREF#2099  -  []  221.56 179.06 0 top
NOREF#2100  -  []  473.79 239.64 0 top
NOREF#2101  -  []  182.57 226.57 90 top
NOREF#2102  -  []  423.61 184.62 90 top
NOREF#2103  -  []  352.24 183.59 90 top
NOREF#2104  -  []  394.66 226.38 90 top
NOREF#2105  -  []  272.55 181.37 0 top
NOREF#2106  -  []  250.5 288.86 0 top
NOREF#2107  -  []  247.78 132.14 90 top
NOREF#2108  -  []  248.61 290.13 90 top
NOREF#2109  -  []  124.35 195.15 0 top
NOREF#2110  -  []  105.93 204.27 90 top
NOREF#2111  -  []  316.97 139.64 0 top
NOREF#2112  -  []  182.57 240.28 90 top
NOREF#2113  -  []  450.03 166.93 0 top
NOREF#2114  -  []  215.96 237.06 0 top
NOREF#2115  -  []  411.52 146.33 90 top
NOREF#2116  -  []  122.15 195.15 0 top
NOREF#2117  -  []  106.76 210.11 90 top
NOREF#2118  -  []  295.96 248.49 0 top
NOREF#2119  -  []  337.09 224.74 90 top
NOREF#2120  -  []  106.29 174.19 90 top
NOREF#2121  -  []  272.25 181.05 90 top
NOREF#2122  -  []  210.86 228.47 90 top
NOREF#2123  -  []  218.13 274.06 90 top
NOREF#2124  -  []  374.88 217.11 0 top
NOREF#2125  -  []  459.28 192.71 90 top
NOREF#2126  -  []  284.77 146.93 90 top
NOREF#2127  -  []  286.12 288.86 90 top
NOREF#2128  -  []  192.47 154.88 90 top
NOREF#2129  -  []  413.71 178.82 0 top
NOREF#2130  -  []  396.55 273.11 0 top
NOREF#2131  -  []  302.71 145.61 90 top
NOREF#2132  -  []  239.33 176.03 0 top
NOREF#2133  -  []  392.04 224.85 90 top
NOREF#2134  -  []  314.71 142.44 90 top
NOREF#2135  -  []  253.72 265.86 90 top
NOREF#2136  -  []  352.24 249.18 90 top
NOREF#2137  -  []  374.34 210.38 90 top
NOREF#2138  -  []  468.01 214.96 0 top
NOREF#2139  -  []  459.28 211.76 0 top
NOREF#2140  -  []  366.88 222.7 0 top
NOREF#2141  -  []  301.56 179.06 0 top
NOREF#2142  -  []  250.73 264.35 90 top
NOREF#2143  -  []  182.57 212.85 90 top
NOREF#2144  -  []  333.4 205.56 0 top
NOREF#2145  -  []  423.61 188.92 90 top
NOREF#2146  -  []  371.48 257.11 0 top
NOREF#2147  -  []  182.82 230.19 90 top
